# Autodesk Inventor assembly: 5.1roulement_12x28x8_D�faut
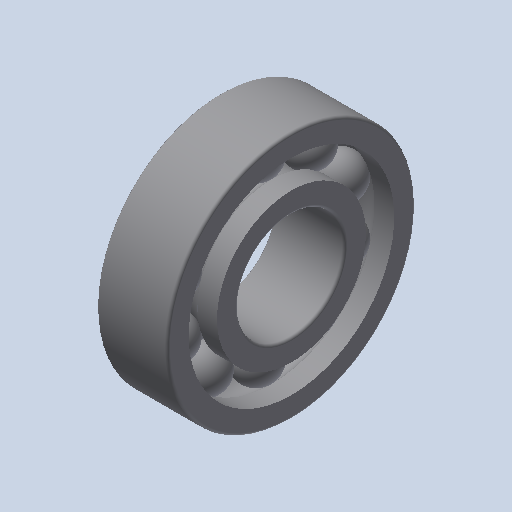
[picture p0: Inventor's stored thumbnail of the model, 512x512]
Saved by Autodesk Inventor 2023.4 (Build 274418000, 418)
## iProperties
Created: 2011-01
Part Number: 5.1roulement_12x28x8_D�faut
Document SubType Name: Assembly
Designer: eric
Mass: 2.73783 g
Surface Area: 33.63 cm^2
Volume: 2.73783 cm^3
Density: 1 g/cm^3
Author: eric
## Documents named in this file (4)
- C:\Users\bruno\Documents\1-Cours-2024-25\TSsI\7-Dynamique\chariot de golf\chariot_de_golf\chariot_de_golf_trolem\5.1roulement_12x28x8_Defaut.iam
- C:\Users\bruno\Documents\1-Cours-2024-25\TSsI\7-Dynamique\chariot de golf\chariot_de_golf\chariot_de_golf_trolem\Roulement_r1rb_Bext27_Defaut.ipt
- C:\Users\bruno\Documents\1-Cours-2024-25\TSsI\7-Dynamique\chariot de golf\chariot_de_golf\chariot_de_golf_trolem\Roulement_r1rb_Eroul27_Defaut.ipt
- C:\Users\bruno\Documents\1-Cours-2024-25\TSsI\7-Dynamique\chariot de golf\chariot_de_golf\chariot_de_golf_trolem\Roulement_r1rb_Bint27_Defaut.ipt
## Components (12 placed, 3 different names)
1. Roulement_r1rb_Bext27_Defaut:1
2. Roulement_r1rb_Eroul27_Defaut:1
3. Roulement_r1rb_Eroul27_Defaut:2
4. Roulement_r1rb_Eroul27_Defaut:3
5. Roulement_r1rb_Eroul27_Defaut:4
6. Roulement_r1rb_Eroul27_Defaut:5
7. Roulement_r1rb_Eroul27_Defaut:6
8. Roulement_r1rb_Eroul27_Defaut:7
9. Roulement_r1rb_Eroul27_Defaut:8
10. Roulement_r1rb_Eroul27_Defaut:9
11. Roulement_r1rb_Eroul27_Defaut:10
12. Roulement_r1rb_Bint27_Defaut:1
